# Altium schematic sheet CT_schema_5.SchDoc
size 282 x 169 mm
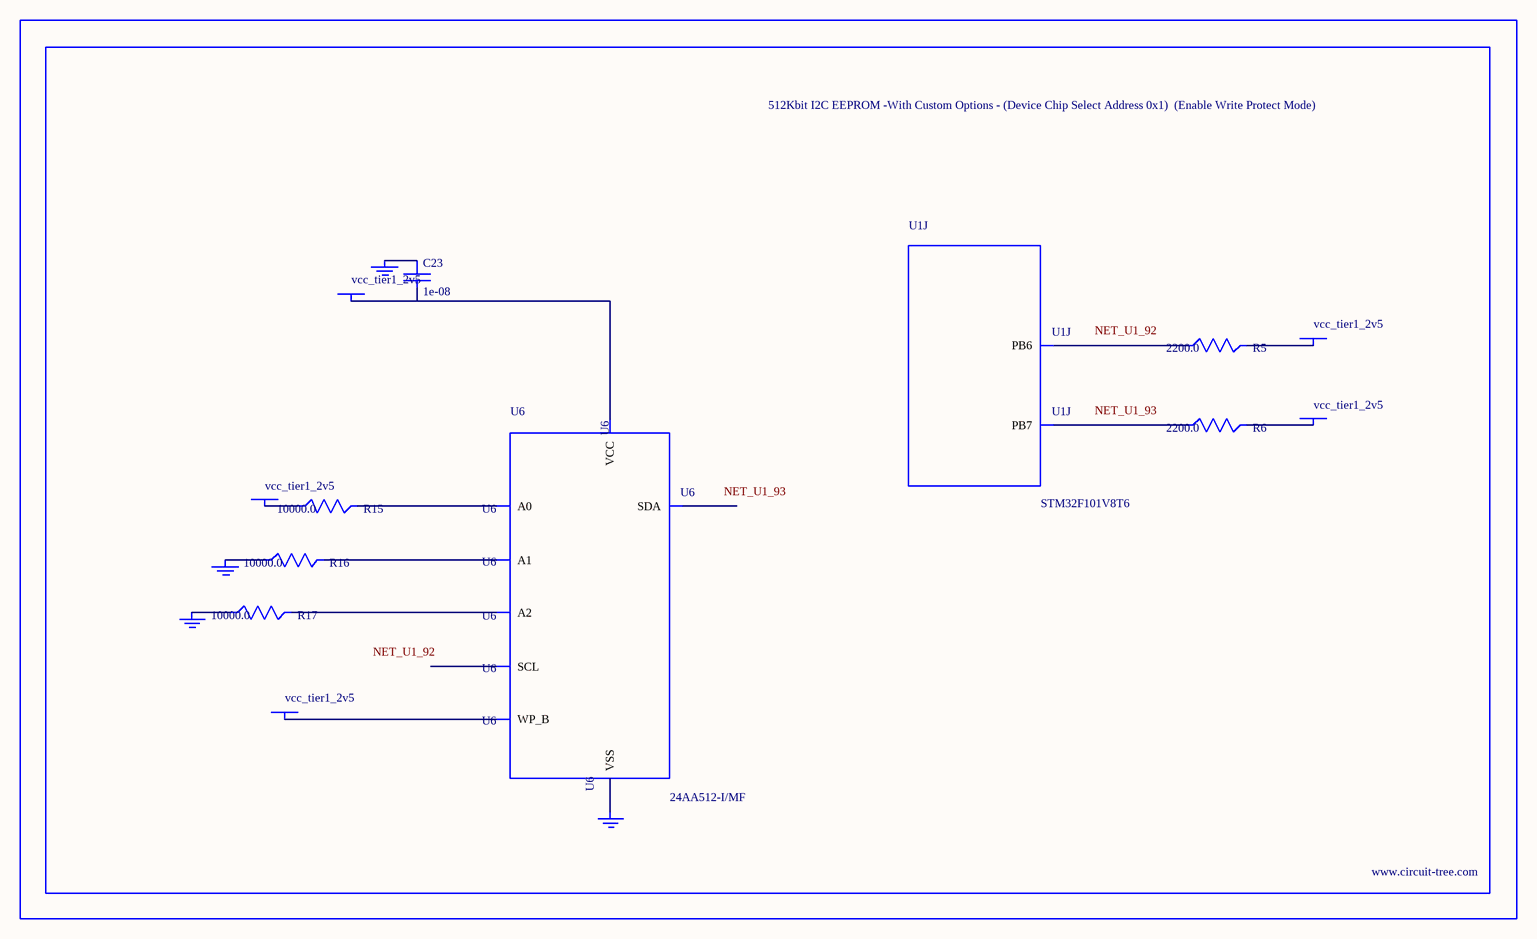
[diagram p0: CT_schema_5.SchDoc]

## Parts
BORDER4  (no value)
C23  1e-08  [C0402]
GND_INSTANCE_4_0  (no value)
GND_INSTANCE_4_1  (no value)
GND_INSTANCE_4_2  (no value)
GND_INSTANCE_4_3  (no value)
POWER_INSTANCE_4_0  vcc_tier1_2v5
POWER_INSTANCE_4_1  vcc_tier1_2v5
POWER_INSTANCE_4_2  vcc_tier1_2v5
POWER_INSTANCE_4_3  vcc_tier1_2v5
POWER_INSTANCE_4_4  vcc_tier1_2v5
R5  2200.0  [R0603]
R6  2200.0  [R0603]
R15  10000.0  [R0603]
R16  10000.0  [R0603]
R17  10000.0  [R0603]
U1  STM32F101V8T6  [LQFP100]  (part J of 10)
U6  24AA512-I/MF  [DFN8-S]

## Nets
NetC23_1: C23.1 GND_INSTANCE_4_2.0(GND)
NetC23_2: C23.2 POWER_INSTANCE_4_2.0(PWR) U6.8(VCC)
NetGND_INSTANCE_4_0_0: GND_INSTANCE_4_0.0(GND) R16.1
NetGND_INSTANCE_4_1_0: GND_INSTANCE_4_1.0(GND) R17.1
NetGND_INSTANCE_4_3_0: GND_INSTANCE_4_3.0(GND) U6.4(VSS)
NetPOWER_INSTANCE_4_0_0: POWER_INSTANCE_4_0.0(PWR) R15.1
NetPOWER_INSTANCE_4_1_0: POWER_INSTANCE_4_1.0(PWR) U6.7(WP_B)
NetPOWER_INSTANCE_4_3_0: POWER_INSTANCE_4_3.0(PWR) R5.2
NetPOWER_INSTANCE_4_4_0: POWER_INSTANCE_4_4.0(PWR) R6.2
NetR5_1: R5.1 U1.92(PB6)
NetR6_1: R6.1 U1.93(PB7)
NetR15_2: R15.2 U6.1(A0)
NetR16_2: R16.2 U6.2(A1)
NetR17_2: R17.2 U6.3(A2)

Not connected (* = marked no-connect by the designer): U6 5(SDA) 6(SCL)

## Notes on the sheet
- Labels drawn without touching a wire or pin: NET_U1_92, NET_U1_93

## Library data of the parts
BORDER4 = BORDER_PAGE4
C23 = C0402C103K3RAC
GND_INSTANCE_4_0-GND_INSTANCE_4_3 = GND
POWER_INSTANCE_4_0-POWER_INSTANCE_4_4 = PWR
R5 R6 = RC0603JR-072K2L
R15-R17 = RC0603JR-0710KL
